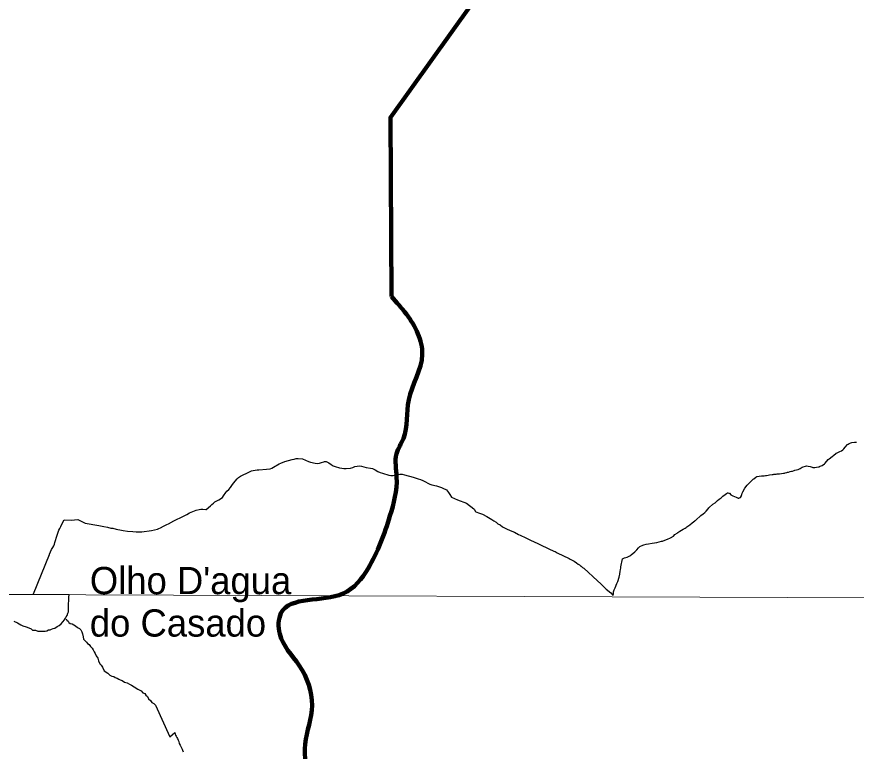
# Model space of a CAD drawing. Extents: x 553962 to 842807, y 8883888 to 9032388.
# Drawn here: x 628002 to 643403, y 8946766 to 8960248 of the extents above; entities that cross this region are included whole.
import ezdxf

# ---------------------------------------------------------------- set-up
doc = ezdxf.new("R2010")
doc.units = 0
doc.header["$LTSCALE"] = 200
for name, color, linetype, lineweight in [('1', 7, 'Continuous', 13), ('12', 7, 'Continuous', 25), ('21', 7, 'Continuous', 25), ('9', 7, 'Continuous', 90)]:
    doc.layers.add(name, color=color, linetype=linetype, lineweight=lineweight)
doc.layers.add('41', color=7, linetype='Continuous')

msp = doc.modelspace()

# ---------------------------------------------------------------- linework, layer by layer
at = {"layer": '1'}
msp.add_line((565315.3, 8949866.8), (791497.7, 8949052.2), dxfattribs=at)
at = {"layer": '12'}
for points in [[(642470.5, 8951998.4), (642488.5, 8952001.9), (642522.6, 8951999.2), (642556.7, 8951992.9), (642592.3, 8951983), (642609.4, 8951976.9), (642626.5, 8951976.6), (642642.7, 8951974.7), (642676.8, 8951977.7), (642721, 8951987.2), (642724.8, 8951990.9), (642735.1, 8951994.5), (642743.5, 8952000), (642776.2, 8952012.3), (642776.2, 8952012.3), (642820.9, 8952041.1), (642834.6, 8952053), (642890.7, 8952119.2), (642906.7, 8952133.2), (642928.9, 8952148.8), (642967.9, 8952182.8), (642985, 8952193.5), (643037.1, 8952235.1), (643053.7, 8952245), (643102.2, 8952265.8), (643135, 8952282.2), (643159.6, 8952300.8), (643178.3, 8952317.8), (643202.9, 8952349.8), (643246, 8952395.7), (643257.2, 8952401.9), (643271.1, 8952413.3), (643302.7, 8952429.5), (643320.6, 8952432.8), (643369.3, 8952438.9), (643405.8, 8952441)], [(631977.1, 8951685.3), (632043.8, 8951765.5), (632068.1, 8951787.6), (632108.7, 8951813.7), (632273.3, 8951897.1), (632308.2, 8951910.2), (632340.4, 8951920.2), (632377.3, 8951927.3), (632410.5, 8951931.4), (632445.5, 8951933.4), (632583, 8951943.7), (632651.1, 8951951.8), (632683.3, 8951961.8), (632714.5, 8951977.9), (632813.6, 8952039.2), (632846.3, 8952056.3), (632917.7, 8952084.4), (633052.1, 8952118.7), (633089.1, 8952126.8), (633126.8, 8952136.8), (633162.7, 8952142.2)], [(633162.7, 8952142.2), (633241, 8952131), (633351.4, 8952085.1), (633389.4, 8952073.2), (633476, 8952053.2), (633512.3, 8952049.3), (633554.8, 8952055.4), (633594.5, 8952068.5), (633634.9, 8952078.5), (633648.8, 8952084.6), (633676.3, 8952083.6), (633727.4, 8952060.7), (633770.1, 8952027.7), (633804.1, 8952004.7), (633842.6, 8951989.7), (633923.6, 8951967.8), (633963.1, 8951960.9), (634004.5, 8951957.9), (634043, 8951958), (634125.1, 8951962.1), (634165.6, 8951972.2), (634207, 8951990.3), (634246.6, 8951999.4), (634288, 8952002.5), (634328.5, 8951997.5), (634368.9, 8951987.6), (634409.5, 8951974.6), (634490.4, 8951962.7), (634530.8, 8951952.8), (634579.8, 8951930.8), (634627.9, 8951901.8), (634668.1, 8951883.9), (634709.8, 8951868.9), (634829.3, 8951833.1), (634866.1, 8951824.1)], [(640395.6, 8950959.1), (640439.6, 8950994.5), (640445, 8950997), (640447, 8951000.5), (640457.8, 8951007.8), (640555.3, 8951093.5), (640594.1, 8951120.7), (640626.7, 8951148.9), (640649.6, 8951173.9), (640686.4, 8951218.1), (640699.1, 8951231), (640711, 8951247), (640763.7, 8951297.4), (640775.4, 8951302.8), (640813.7, 8951328.4), (640837.7, 8951348), (640857.9, 8951367.2), (640891.5, 8951395.5), (640923.9, 8951418.5), (640957.6, 8951446.5), (641002, 8951475.6), (641024.2, 8951496.1), (641040.4, 8951506.2), (641048.4, 8951506.8), (641063.8, 8951505.7), (641076.1, 8951500.8), (641103, 8951472.9), (641113.2, 8951465), (641125.4, 8951459), (641140.6, 8951455), (641169.7, 8951440.6), (641200.2, 8951430.5), (641213.3, 8951424.4), (641238.7, 8951409.4), (641250.3, 8951409.1), (641257, 8951415.1), (641263.6, 8951416.6), (641271.5, 8951423.5), (641278.8, 8951426.2), (641300.2, 8951451.3), (641301.2, 8951463.4), (641305.1, 8951471.8), (641310.1, 8951499.8), (641314, 8951513.2), (641320.4, 8951528.1), (641359.3, 8951592.4), (641405.6, 8951650.4), (641442.9, 8951693.2), (641484.3, 8951731.3), (641515.2, 8951757.2), (641526.5, 8951768.3), (641559, 8951794.4), (641579.3, 8951807.2), (641667.6, 8951821), (641713.1, 8951823.5), (641738.9, 8951828.1), (641757.8, 8951829.8), (641786.9, 8951836), (641814.4, 8951840), (641860.7, 8951842.5), (641877.2, 8951846.8), (641891.3, 8951848.7), (641906.2, 8951849), (641921.9, 8951853), (641936.1, 8951853.2), (641951.8, 8951855.2), (641995, 8951856.3), (642070.3, 8951868.1), (642085.2, 8951872.2), (642100.9, 8951874.6), (642130, 8951881.9), (642144.9, 8951887.1), (642160.5, 8951889.6), (642189.7, 8951897.8), (642218.7, 8951904.1), (642234.4, 8951909.5), (642263.5, 8951916.8), (642278.1, 8951923.3), (642336.6, 8951938.4), (642365, 8951949.3), (642376.5, 8951955.1), (642413.4, 8951978.7), (642427.4, 8951986.2), (642470.5, 8951998.4)], [(634866.1, 8951824.1), (634873.4, 8951824.1), (634910.2, 8951826.2), (634950.7, 8951837.2), (634989.1, 8951847.3), (635028.1, 8951852.4), (635071.3, 8951849.5), (635114.6, 8951840.5), (635272.6, 8951793.7), (635367.2, 8951768.8), (635408.9, 8951751.8), (635451.4, 8951736.9), (635498.6, 8951712.9), (635544.2, 8951684), (635579.4, 8951666), (635619.9, 8951654), (635700.8, 8951640.1), (635740.5, 8951628.2), (635792.4, 8951609.2), (635828.7, 8951590.2), (635872.5, 8951570.3), (635883.6, 8951562.3), (635922.4, 8951513.3), (635950.1, 8951475.3), (635979.6, 8951429.2), (636087.1, 8951379.3), (636253.1, 8951319.5), (636386.5, 8951215.6), (636391.7, 8951209.6), (636419.7, 8951164.5), (636421.7, 8951160.5), (636421.7, 8951160.5), (636421.7, 8951160.5)], [(628309.2, 8949653.4), (628599.7, 8950377.9), (628601.3, 8950384.9), (628641.4, 8950470.1), (628663, 8950503.2), (628681.3, 8950538.3), (628691.8, 8950567.4), (628700.4, 8950599.4), (628711, 8950631.5), (628727.3, 8950696.6), (628774.6, 8950822.9), (628788.9, 8950856), (628806.9, 8950888.1), (628840.8, 8950956.2), (628872.2, 8951013.3), (628996.9, 8951009.5), (629121.2, 8951016.8), (629253.8, 8950950.8), (629505.9, 8950912.2), (629601.8, 8950889.3), (629665.7, 8950879.4), (629728.8, 8950861.5), (629762.5, 8950857.5), (629825.6, 8950843.6), (629857.5, 8950834.6), (629889.5, 8950829.7), (629956.5, 8950815.8), (630035.3, 8950806.9), (630130.2, 8950799), (630192.3, 8950791.1), (630294.1, 8950795.2), (630475.3, 8950814.6), (630582.1, 8950842.8), (630610.8, 8950852.8), (630639.6, 8950867.9), (630696.5, 8950894.1), (630755.1, 8950927.2), (630784, 8950940.3), (630880.8, 8950995.5), (630942.3, 8951026.6), (631001.9, 8951051.8), (631119.9, 8951113.1), (631172.4, 8951142.2), (631232.1, 8951169.3), (631292.6, 8951189.5), (631346.6, 8951202.6), (631380.4, 8951208.6), (631413.7, 8951209.7), (631469.4, 8951200.8), (631474.6, 8951200.8), (631553, 8951268), (631581, 8951297.1), (631608.2, 8951320.2), (631637.5, 8951342.2), (631707.2, 8951377.4), (631776.4, 8951422.6), (631796.8, 8951451.7), (631836.1, 8951514.8), (631854.5, 8951538.9), (631890.1, 8951573), (631921.4, 8951606.1), (631949.1, 8951643.2), (631977.1, 8951685.3), (631977.1, 8951685.3)], [(636421.7, 8951160.5), (636492.6, 8951137.6), (636543.8, 8951117.6), (636626.9, 8951075.7), (636719.5, 8951017.8), (636751.5, 8950995.8), (636795.3, 8950967.8), (636826.1, 8950942.8), (636870.7, 8950918.8), (636915.4, 8950886.9), (636996.5, 8950842.9), (637085.1, 8950803), (637131.6, 8950784.1), (637204.7, 8950745.1)], [(639116.2, 8950297.4), (639149.8, 8950312.8), (639201.4, 8950330), (639225.8, 8950341.2), (639251, 8950352), (639254.3, 8950354.5), (639265.5, 8950361.8), (639275.1, 8950369.6), (639340.1, 8950423.9), (639377.5, 8950461.2), (639409.6, 8950499.5), (639433.2, 8950522.9), (639488.6, 8950549.3), (639509.1, 8950557.4), (639550.9, 8950566.9), (639593.5, 8950572.4), (639658.3, 8950586.3), (639703.6, 8950591.1), (639744.3, 8950599.4), (639786.9, 8950612), (639828.7, 8950619.4), (639850, 8950624.7), (639890, 8950637.6), (639937.9, 8950655.7), (639994.2, 8950681.9), (640048.1, 8950716.4), (640078.5, 8950742.4), (640115.7, 8950767), (640133.5, 8950781.2), (640151.5, 8950793.1), (640167.6, 8950806.8), (640226.6, 8950841.8), (640263.4, 8950861.3), (640263.4, 8950861.3), (640280.4, 8950873), (640297.6, 8950886.7), (640316.3, 8950898), (640351.7, 8950923.7), (640395.6, 8950959.1)], [(637204.7, 8950745.1), (637236.4, 8950731.9), (637342.1, 8950681.2), (637402.5, 8950654.2), (637429.5, 8950639.7), (637442.2, 8950635.2), (637481.3, 8950617.9), (637571.5, 8950575), (637632.7, 8950543.3), (637724.2, 8950501.8), (637761.9, 8950483), (637855.8, 8950440.2), (637882.2, 8950429.6), (637917.4, 8950409.5), (638134, 8950306.5), (638157.9, 8950291.9), (638228.5, 8950253.9), (638272.8, 8950224.6), (638304.2, 8950197.7), (638316.9, 8950191.8), (638323.7, 8950184.3), (638335.4, 8950179.9), (638341.5, 8950174.2), (638346.7, 8950171.6), (638352.3, 8950164.8), (638359.3, 8950163), (638363.3, 8950157.6), (638382.1, 8950140), (638404.6, 8950123.8), (638657.4, 8949892.2), (638716.1, 8949835.5), (638775.8, 8949782.1), (638818.1, 8949741), (638898.3, 8949671.3), (638932.1, 8949635.9), (638944.8, 8949626.3), (638949.6, 8949652.2), (638952.9, 8949690.6), (638957.5, 8949711.3), (638963.7, 8949729.7), (638981, 8949766.6), (639010.6, 8949844.8), (639027.5, 8949883.2), (639052, 8949959.9), (639066.5, 8950015.8), (639075.2, 8950073.3), (639081, 8950095.8), (639085, 8950131.7), (639085.5, 8950153.3), (639116.2, 8950297.4)], [(628906.4, 8949193.4), (628921.3, 8949173.3), (628943.6, 8949150.6), (628956, 8949130.5), (628983.3, 8949110.3), (629015.8, 8949102.6), (629048.2, 8949084.8), (629080.5, 8949064.6), (629117.8, 8949036.8), (629155.2, 8949016.5), (629177.5, 8948991.3), (629197.3, 8948958.7), (629204.5, 8948921.1), (629221.6, 8948865.9), (629226.2, 8948820.8), (629261, 8948788), (629283.4, 8948770.3), (629298.2, 8948742.7), (629330.6, 8948725), (629352.8, 8948687.2), (629385, 8948654.5), (629404.8, 8948624.3), (629422.1, 8948591.7), (629441.8, 8948556.5), (629459, 8948516.3), (629488.7, 8948473.6), (629503.3, 8948423.4), (629522.9, 8948370.7), (629552.7, 8948342.9), (629572.5, 8948307.8), (629604.5, 8948240), (629669.2, 8948197)], [(629669.2, 8948197), (629708.9, 8948159.2), (629743.8, 8948146.4), (629783.8, 8948136.1), (629808.6, 8948118.4), (629841.1, 8948105.7), (629875.9, 8948088), (629898.4, 8948077.8), (629935.8, 8948062.5), (629978.1, 8948034.7), (630025.5, 8948021.9), (630067.8, 8947994.1), (630107.7, 8947976.3), (630157.5, 8947945.9), (630219.7, 8947905.4), (630282, 8947872.5), (630311.8, 8947839.7), (630351.7, 8947824.4), (630368.9, 8947791.8), (630401.2, 8947769), (630421, 8947728.8), (630455.7, 8947696.1), (630480.5, 8947660.8), (630515.3, 8947640.6), (630547.6, 8947610.3), (630810.8, 8947030.3)], [(630810.8, 8947030.3), (630898.9, 8947107.3), (630908.8, 8947087.2), (630916.1, 8947062.1), (630926, 8947042), (630938.3, 8947019.4), (630948.1, 8946999.3), (630960.4, 8946969.2), (630977.7, 8946941.6), (630980, 8946909), (630999.7, 8946878.8), (631017, 8946838.7), (631034.2, 8946803.5), (631041.5, 8946783.4), (631056.3, 8946755.8)]]:
    msp.add_lwpolyline(points, dxfattribs=at)
at = {"layer": '21'}
msp.add_lwpolyline([(627948.7, 8949152.7), (628014.1, 8949120.8), (628075.7, 8949086.9), (628110.6, 8949066.7), (628173, 8949048.9), (628225.4, 8949033.6), (628265.2, 8949010.9), (628287.6, 8948988.2), (628315.1, 8948988.1), (628342.5, 8948985.4), (628384.9, 8948970.2), (628409.9, 8948970.1), (628442.4, 8948969.9), (628474.9, 8948969.7), (628499.9, 8948969.6), (628525, 8948972), (628555, 8948976.8), (628582.6, 8948994.2), (628612.6, 8948994), (628640.2, 8949006.4), (628670.3, 8949021.2), (628702.8, 8949023.6), (628745.5, 8949053.4), (628778.1, 8949073.2), (628818.4, 8949105.5), (628848.6, 8949140.4), (628878.8, 8949175.3), (628896.5, 8949205.2), (628909.2, 8949232.7), (628924.4, 8949257.6), (628937.2, 8949297.6), (628949.8, 8949325), (628950, 8949352.6), (628950.3, 8949387.6), (628952.9, 8949412.6), (628953.3, 8949462.7), (628953.4, 8949482.7), (628953.7, 8949520.2), (628953.8, 8949540.2), (628954, 8949562.7), (628954.2, 8949595.3), (628960.2, 8949636.4), (627600.1, 8949642.9)], dxfattribs=at)
at = {"layer": '9'}
msp.add_lwpolyline([(637260.6, 8972975.8), (637076.8, 8961505.7), (634855.7, 8958401.3), (634875.3, 8955110.3)], dxfattribs=at)
for points in [[(637260.6, 8972975.8), (641524.5, 8971056.2), (652526.1, 8965412.7), (653164.3, 8965062.8), (670790.5, 8953770.1), (686194, 8943929.9), (696283.3, 8937647.1)], [(630387.4, 8939797.8), (630434.2, 8940142.1), (630686.5, 8940523.6), (631192.1, 8941084.2), (631927.5, 8941519.8), (632256.1, 8941901.8), (632534.2, 8942207.6), (633141.9, 8942718.3), (633623.2, 8943101.4), (634002.9, 8943433.2), (634103.5, 8943636.5), (634126.4, 8944067), (633968.9, 8944876), (633685.2, 8945506.9), (633295.3, 8946896.6), (633418.3, 8947606.3), (633184.9, 8948338.8), (632825.2, 8948918.6), (632848.4, 8949298.5), (633991.4, 8949661), (634446.8, 8950119.9), (634848.2, 8951084.8), (634971.3, 8951794.5), (634968.7, 8952224.9), (635094.3, 8952504.3), (635191.9, 8953213.8), (635441.4, 8954051.1), (635362.8, 8954430.2), (634875.3, 8955110.3)]]:
    msp.add_spline(points, degree=3, dxfattribs=at)

# ---------------------------------------------------------------- texts
at = {"layer": '41'}
for s, p in [("Olho D'agua", (629342.2, 8949648.8)), ('do Casado', (629342.2, 8948869.8))]:
    msp.add_text(s, height=500, dxfattribs=at).set_placement(p)

doc.saveas('drawing.dxf')
